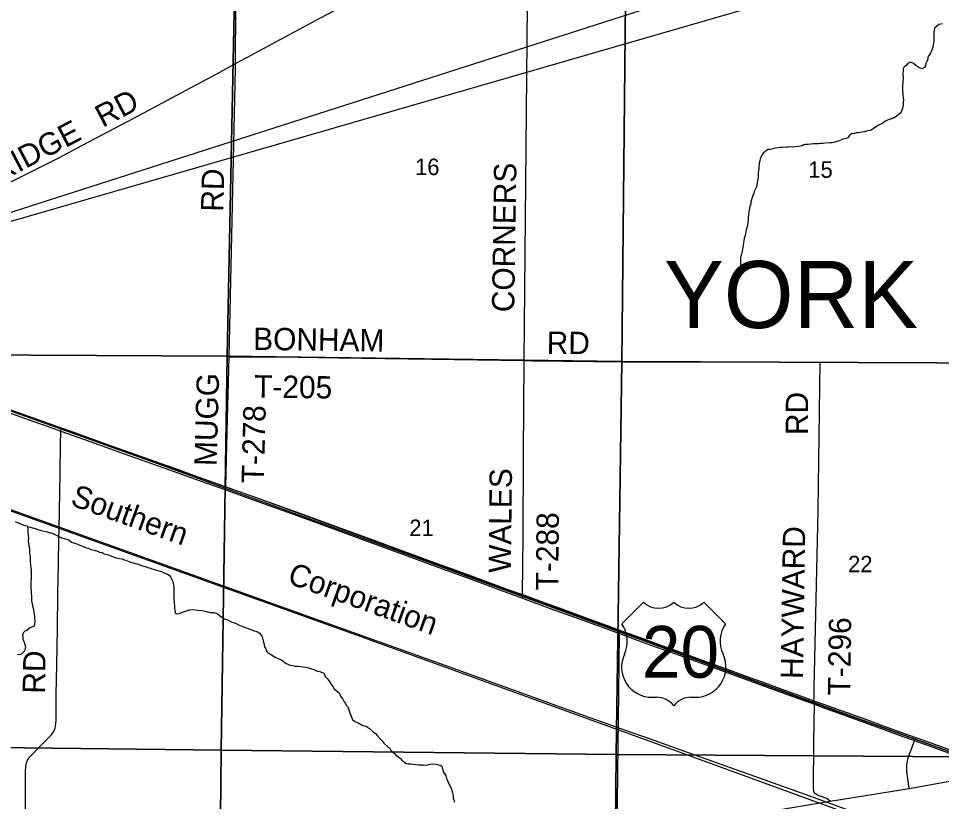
# Model space of a CAD drawing. Extents: x 0 to 34, y 0 to 22.
# Drawn here: x 4.651 to 6.998, y 16.061 to 18.051 of the extents above; entities that cross this region are included whole.
import ezdxf

# ---------------------------------------------------------------- set-up
doc = ezdxf.new("R2010")
doc.units = 0
for name, color, linetype in [('Default', 7, 'Continuous'), ('GM_X_County_Road', 7, 'Continuous'), ('GM_X_County_Road_Text', 7, 'Continuous'), ('GM_X_Minor_River', 7, 'Continuous'), ('GM_X_Rail_Line', 7, 'Continuous'), ('GM_X_Rail_Line_Text', 7, 'Continuous'), ('GM_X_Section', 7, 'Continuous'), ('GM_X_Section_Text', 7, 'Continuous'), ('GM_X_Township_Road', 7, 'Continuous'), ('GM_X_Township_Road_Text', 7, 'Continuous'), ('GM_X_Township_Text', 7, 'Continuous'), ('GM_X_US_Location', 7, 'Continuous'), ('GM_X_US_Route', 7, 'Continuous'), ('GM_X_US_Shield', 7, 'Continuous'), ('SH_Text', 7, 'Continuous')]:
    doc.layers.add(name, color=color, linetype=linetype)

msp = doc.modelspace()

# ---------------------------------------------------------------- linework, layer by layer
at = {"layer": 'Default'}
msp.add_lwpolyline([(3.8857, 17.3198), (5.25, 16.8357), (6.6044, 16.3383), (8.5432, 15.6366)], dxfattribs=at)
at = {"layer": 'GM_X_County_Road'}
for points in [[(4.5879, 17.6151), (4.6791, 17.6602), (4.7547, 17.6984), (4.8116, 17.7285), (4.9444, 17.7981), (5.0773, 17.8691), (5.1548, 17.9107), (5.2026, 17.9368), (5.2298, 17.9517), (5.3067, 17.9926), (5.3765, 18.0305), (5.4168, 18.0526), (5.4594, 18.0741), (5.5554, 18.1209), (5.7021, 18.1923), (5.7858, 18.2331), (5.8346, 18.2596), (5.9044, 18.2995), (5.9372, 18.3188), (5.9416, 18.3214)], [(6.7149, 16.0617), (6.9162, 16.094), (6.91, 16.1373), (6.9103, 16.1561), (6.9143, 16.1752), (6.9228, 16.1968), (6.9296, 16.2157), (6.9325, 16.2234)], [(4.6673, 15.5158), (4.8067, 15.5856), (4.9325, 15.6484), (4.9491, 15.6559), (4.9713, 15.6652), (5.0005, 15.6759), (5.0239, 15.6838), (5.165, 15.7242), (5.3194, 15.7665), (5.4913, 15.8144), (5.6607, 15.8606), (5.7319, 15.8819), (5.8085, 15.906), (5.8772, 15.9212), (5.9478, 15.9336), (6.1734, 15.9709), (6.2896, 15.9914), (6.4702, 16.0208), (6.7149, 16.0617)]]:
    msp.add_lwpolyline(points, dxfattribs=at)
at = {"layer": 'GM_X_Minor_River'}
for points in [[(7.0002, 18.0376), (6.996, 18.0368), (6.9915, 18.036), (6.9843, 18.0303), (6.9802, 18.0265), (6.9787, 18.0158), (6.9783, 18.0101), (6.9784, 17.9961), (6.9777, 17.9889), (6.9769, 17.9832), (6.9758, 17.9786), (6.9743, 17.9733), (6.9725, 17.9691), (6.9691, 17.9619), (6.9653, 17.9562), (6.9634, 17.952), (6.9631, 17.9478), (6.9608, 17.9417), (6.9586, 17.9367), (6.9571, 17.9314), (6.9548, 17.9269), (6.9484, 17.9234), (6.9408, 17.9272), (6.9328, 17.9321), (6.9267, 17.9374), (6.921, 17.9396), (6.9168, 17.9396), (6.9119, 17.9365), (6.9085, 17.932), (6.9032, 17.9285), (6.9009, 17.9232), (6.9002, 17.9171), (6.8999, 17.9129), (6.8999, 17.908), (6.9003, 17.9038), (6.9003, 17.8996), (6.9, 17.8932), (6.8996, 17.8871), (6.8992, 17.8825), (6.8989, 17.8768), (6.8989, 17.867), (6.8997, 17.8609), (6.8998, 17.8563), (6.9006, 17.8495), (6.901, 17.8446), (6.9006, 17.8385), (6.9003, 17.8332)], [(6.9003, 17.8332), (6.8995, 17.826), (6.898, 17.821), (6.8962, 17.8168), (6.8947, 17.8115), (6.8826, 17.8027), (6.8784, 17.8), (6.8739, 17.797), (6.8651, 17.795), (6.861, 17.7931), (6.8557, 17.7904), (6.8492, 17.7855), (6.8439, 17.7831), (6.8379, 17.7805), (6.8326, 17.777), (6.8265, 17.7724), (6.822, 17.7694), (6.8171, 17.7671), (6.8106, 17.7659), (6.8015, 17.7632), (6.7958, 17.7624), (6.7913, 17.762), (6.7863, 17.7608), (6.7822, 17.7604), (6.7772, 17.7593), (6.7693, 17.7581), (6.7632, 17.7535), (6.7598, 17.7482), (6.7545, 17.7466), (6.75, 17.7451), (6.7451, 17.7436), (6.7375, 17.7405), (6.7318, 17.7386), (6.7242, 17.7362), (6.7197, 17.7355), (6.7144, 17.7354), (6.7022, 17.7346), (6.6969, 17.7338), (6.6912, 17.7334), (6.6851, 17.733), (6.6779, 17.733), (6.6719, 17.7326), (6.6654, 17.7322), (6.6586, 17.7314), (6.6525, 17.731), (6.6476, 17.7306), (6.6434, 17.7279), (6.6335, 17.7256), (6.626, 17.7248), (6.6184, 17.7247), (6.6131, 17.7251), (6.6085, 17.7247), (6.6036, 17.7243), (6.5926, 17.7238), (6.5876, 17.7234), (6.5831, 17.723), (6.5755, 17.7219), (6.5706, 17.7207), (6.5664, 17.7195), (6.5615, 17.7188), (6.5573, 17.718), (6.5527, 17.7161), (6.5448, 17.7088), (6.5407, 17.702), (6.5373, 17.6943), (6.5362, 17.6898), (6.5347, 17.6833), (6.5336, 17.6734), (6.5336, 17.6693), (6.5318, 17.6601), (6.5314, 17.656), (6.5315, 17.6468), (6.5304, 17.6385), (6.5292, 17.6339), (6.5285, 17.6297), (6.5274, 17.6236), (6.5218, 17.6118), (6.521, 17.6077), (6.5173, 17.5993), (6.5135, 17.5852), (6.5128, 17.5803), (6.5106, 17.5731), (6.5091, 17.5651), (6.5072, 17.5521), (6.5065, 17.5468), (6.5065, 17.5396), (6.5054, 17.5328), (6.5047, 17.5248), (6.5017, 17.5141), (6.5006, 17.51), (6.4995, 17.505), (6.4984, 17.5004), (6.4965, 17.4921), (6.4954, 17.4864), (6.494, 17.4757), (6.4932, 17.47), (6.4921, 17.4647), (6.491, 17.459), (6.4891, 17.4522), (6.488, 17.4476), (6.4873, 17.4423)], [(6.4873, 17.4423), (6.4866, 17.4366), (6.4867, 17.4108)], [(4.642, 16.7729), (4.6519, 16.7684), (4.6671, 16.7628), (4.6732, 16.7613), (4.6744, 16.7537), (4.6748, 16.7492), (4.6748, 16.7439), (4.6752, 16.7397), (4.6756, 16.7359), (4.676, 16.7317), (4.6753, 16.723), (4.6761, 16.7169), (4.6773, 16.7108), (4.6784, 16.7051), (4.6785, 16.6983), (4.6792, 16.693), (4.6797, 16.688), (4.6801, 16.6808), (4.6805, 16.6732), (4.6809, 16.6694), (4.6813, 16.6645), (4.6817, 16.6607), (4.6821, 16.6558), (4.6829, 16.6497), (4.6833, 16.6451), (4.6833, 16.6315), (4.683, 16.6258)], [(4.6734, 16.7603), (4.6934, 16.755), (4.6998, 16.752), (4.7063, 16.7508), (4.712, 16.749), (4.7215, 16.7471), (4.731, 16.7441), (4.7367, 16.7426), (4.7451, 16.7385), (4.7508, 16.7359), (4.755, 16.734), (4.761, 16.7313), (4.7664, 16.7291), (4.7789, 16.7257), (4.7858, 16.7201), (4.7941, 16.7178), (4.8135, 16.7099), (4.8238, 16.7058), (4.8291, 16.7047), (4.8345, 16.7017), (4.8432, 16.6998), (4.8516, 16.6972), (4.8569, 16.695), (4.8633, 16.6939), (4.8691, 16.6908), (4.877, 16.6886), (4.8873, 16.6848), (4.8945, 16.6818), (4.8991, 16.6807), (4.9078, 16.6785), (4.9143, 16.6774), (4.9196, 16.6755), (4.9242, 16.674), (4.9318, 16.6706), (4.9386, 16.6688), (4.9428, 16.6676), (4.9478, 16.6661), (4.9535, 16.6647), (4.9614, 16.6613), (4.9671, 16.6602), (4.9755, 16.6572), (4.982, 16.6553), (4.9861, 16.6542), (4.9903, 16.6527), (4.9945, 16.6516), (5.0021, 16.6493), (5.0074, 16.6471), (5.0143, 16.6456), (5.0227, 16.6414), (5.0295, 16.6384), (5.0341, 16.6365), (5.0371, 16.6324), (5.0406, 16.6252), (5.0433, 16.6203), (5.044, 16.6157), (5.0448, 16.6104), (5.046, 16.6055), (5.046, 16.6013), (5.046, 16.5963), (5.0461, 16.5743), (5.0466, 16.5679), (5.0474, 16.5557), (5.0478, 16.5508), (5.049, 16.5443), (5.0494, 16.5394), (5.0539, 16.5379), (5.0592, 16.5387), (5.0729, 16.5437), (5.0861, 16.5483), (5.0945, 16.5487), (5.1066, 16.5476), (5.1176, 16.5462), (5.1287, 16.5439), (5.1385, 16.5417), (5.1431, 16.5417), (5.1477, 16.5414), (5.1526, 16.5399), (5.1568, 16.5376), (5.1617, 16.5338), (5.1678, 16.5297), (5.1747, 16.5252), (5.1827, 16.5229), (5.1933, 16.5165), (5.2032, 16.5139), (5.2082, 16.5109), (5.2135, 16.5083), (5.2196, 16.5068), (5.2264, 16.503), (5.2336, 16.5011), (5.2382, 16.4993), (5.2443, 16.4974), (5.2492, 16.4947), (5.2546, 16.4936), (5.2599, 16.4914), (5.2641, 16.4884), (5.2683, 16.4834), (5.2706, 16.4793), (5.2729, 16.469), (5.2748, 16.4637), (5.2764, 16.4542), (5.2795, 16.4489)], [(4.683, 16.6258), (4.6823, 16.6193), (4.6819, 16.6155), (4.682, 16.6064), (4.6824, 16.6011), (4.6828, 16.5973), (4.6832, 16.5897), (4.6836, 16.5844), (4.6836, 16.5756), (4.684, 16.5711), (4.686, 16.5631), (4.6875, 16.5547), (4.6887, 16.5491), (4.6895, 16.5422), (4.6903, 16.5369), (4.6911, 16.5312), (4.6918, 16.5263), (4.6923, 16.5213), (4.6923, 16.5172), (4.6915, 16.5107), (4.6904, 16.5069), (4.6791, 16.5011), (4.6723, 16.4958), (4.6673, 16.4935), (4.6636, 16.4901), (4.6613, 16.484), (4.6617, 16.4775), (4.6621, 16.4737), (4.6652, 16.4661), (4.6667, 16.4597), (4.6683, 16.454), (4.6679, 16.4498), (4.6657, 16.4433), (4.6597, 16.4365), (4.6559, 16.4346), (4.6479, 16.4338)], [(5.2795, 16.4489), (5.2825, 16.4425), (5.2863, 16.4379), (5.2943, 16.4338), (5.3035, 16.4274), (5.3088, 16.4255), (5.3179, 16.4218), (5.3229, 16.4184), (5.3297, 16.4127), (5.3355, 16.4097), (5.3412, 16.4074), (5.3484, 16.4063), (5.3541, 16.4052), (5.3632, 16.4045), (5.3742, 16.403), (5.3814, 16.4027), (5.3883, 16.4004), (5.3936, 16.3993), (5.4016, 16.3963), (5.4103, 16.3926), (5.4168, 16.3911), (5.4225, 16.3888), (5.427, 16.3877), (5.4305, 16.379), (5.4355, 16.3733), (5.4389, 16.3692), (5.4435, 16.3635), (5.4469, 16.3574), (5.4511, 16.3525), (5.4531, 16.3483), (5.4626, 16.3396), (5.4668, 16.3362), (5.4683, 16.3321), (5.4714, 16.326), (5.4752, 16.3207), (5.479, 16.3146), (5.4825, 16.3101), (5.4844, 16.3056), (5.4882, 16.3014), (5.4905, 16.2938), (5.4936, 16.2866), (5.4948, 16.282), (5.4967, 16.2779), (5.5001, 16.2695), (5.5062, 16.2643), (5.5142, 16.2609), (5.5245, 16.2548), (5.5355, 16.2515), (5.5435, 16.2466), (5.5527, 16.2379), (5.5588, 16.2341), (5.5634, 16.2277), (5.5718, 16.2194), (5.5756, 16.2148), (5.5798, 16.2088), (5.5897, 16.2001), (5.5939, 16.1971), (5.5969, 16.1925), (5.6008, 16.1876), (5.6053, 16.185), (5.6107, 16.1789), (5.6149, 16.1763), (5.6221, 16.1706), (5.6267, 16.1649), (5.6316, 16.1619), (5.6366, 16.1577), (5.6415, 16.1563), (5.6476, 16.1563), (5.6552, 16.1556), (5.6601, 16.1552), (5.6677, 16.1541), (5.6799, 16.1538), (5.686, 16.1534), (5.692, 16.1542), (5.6973, 16.1554), (5.7046, 16.1562), (5.7114, 16.1554), (5.7194, 16.1543), (5.7235, 16.1532), (5.7277, 16.151), (5.7281, 16.1468), (5.7297, 16.1415), (5.732, 16.1354), (5.735, 16.1305), (5.7373, 16.1263), (5.7389, 16.1191), (5.7416, 16.1142), (5.7446, 16.1077), (5.7481, 16.1013), (5.7523, 16.0922), (5.7535, 16.0865), (5.7554, 16.0789), (5.7558, 16.0736), (5.7566, 16.069), (5.7585, 16.063), (5.7589, 16.0588)]]:
    msp.add_lwpolyline(points, dxfattribs=at)
at = {"layer": 'GM_X_Rail_Line'}
for points in [[(2.3438, 17.8832), (3.2394, 17.556), (3.7037, 17.3885), (4.1527, 17.2251), (5.0251, 16.9129), (5.72, 16.6602), (6.7111, 16.2981), (7.2308, 16.1113), (7.9999, 15.8344), (8.5456, 15.6361), (8.9, 15.5035)], [(2.1205, 17.682), (2.6475, 17.5103), (3.1194, 17.3438), (3.8981, 17.0634), (4.4129, 16.8774), (5.5123, 16.484), (6.2938, 16.2008), (7.1773, 15.8785), (7.9469, 15.6046), (8.6994, 15.3378), (8.9, 15.264)], [(4.3626, 16.8993), (4.9898, 16.6747), (5.3844, 16.533), (5.7561, 16.3995), (6.08, 16.2832), (6.1965, 16.2416), (6.2568, 16.2199), (6.33, 16.1936), (6.5817, 16.1037), (6.6739, 16.0713), (6.9385, 15.9745), (7.0187, 15.9431)]]:
    msp.add_lwpolyline(points, dxfattribs=at)
at = {"layer": 'GM_X_Section'}
for points in [[(4.1997, 18.1993), (5.2018, 18.1949), (5.1818, 17.1932), (4.1831, 17.1984)], [(5.2018, 18.1949), (6.1951, 18.1802), (6.185, 17.1797), (5.1818, 17.1932)], [(7.2022, 18.181), (7.1859, 17.1752), (6.185, 17.1797), (6.1951, 18.1802)], [(4.1831, 17.1984), (5.1818, 17.1932), (5.166, 16.1912), (4.1651, 16.2036)], [(5.1818, 17.1932), (6.185, 17.1797), (6.1703, 16.1807), (5.166, 16.1912)], [(6.185, 17.1797), (7.1859, 17.1752), (7.1762, 16.1739), (6.1703, 16.1807)], [(4.1651, 16.2036), (5.166, 16.1912), (5.1562, 15.1911), (4.1541, 15.2001)], [(5.166, 16.1912), (6.1703, 16.1807), (6.1617, 15.1831), (5.1562, 15.1911)], [(7.1762, 16.1739), (7.1686, 15.1654), (6.1617, 15.1831), (6.1703, 16.1807)]]:
    msp.add_lwpolyline(points, close=True, dxfattribs=at)
at = {"layer": 'GM_X_Township_Road'}
msp.add_line((6.9162, 16.094), (7.0561, 16.1195), dxfattribs=at)
for points in [[(5.2027, 17.9498), (5.2148, 19.617), (5.2148, 19.7745), (5.2168, 19.9602), (5.2193, 20.1515), (5.2185, 20.2104), (5.2187, 20.22), (5.2204, 20.2273), (5.2209, 20.2283), (5.2253, 20.2361), (5.2264, 20.238)], [(5.9368, 17.1818), (5.9465, 18.1768), (5.9503, 18.3268)], [(5.1865, 17.1917), (5.2025, 17.924), (5.2026, 17.9368), (5.2027, 17.9498)], [(5.1784, 16.8529), (5.1785, 16.8612), (5.1827, 17.0344), (5.1854, 17.1595), (5.1865, 17.1917)], [(5.1865, 17.1917), (5.3114, 17.1916), (5.4642, 17.1891), (5.9368, 17.1818), (5.9591, 17.1811), (6.1898, 17.1786), (6.6892, 17.1776), (7.1906, 17.1758)], [(5.9322, 16.578), (5.9323, 16.5867), (5.9339, 16.7333), (5.935, 16.9442), (5.9368, 17.1818)], [(6.6824, 16.7244), (6.684, 16.8014), (6.6892, 17.1776)], [(4.7539, 16.7519), (4.7547, 16.7997), (4.7566, 16.8939), (4.7576, 16.9678), (4.7587, 17.0023), (4.7591, 17.0108)], [(4.6683, 16.0047), (4.6686, 16.0899), (4.6689, 16.1374), (4.6695, 16.1492), (4.6711, 16.1594), (4.6735, 16.1661), (4.6794, 16.1748), (4.7075, 16.2029), (4.7338, 16.2297), (4.7409, 16.239), (4.7442, 16.2481), (4.7456, 16.2583), (4.7463, 16.2684), (4.7469, 16.333), (4.7484, 16.4091), (4.7501, 16.4993), (4.751, 16.5903), (4.7522, 16.6632), (4.7536, 16.732), (4.7539, 16.7519)], [(6.6738, 16.3172), (6.6739, 16.3274), (6.6746, 16.3501), (6.6824, 16.7244)], [(6.1734, 15.9709), (6.1751, 16.1354), (6.1772, 16.3363), (6.1789, 16.4878), (6.1793, 16.4965)], [(6.6738, 16.2113), (6.675, 16.308), (6.6738, 16.3172)], [(6.7149, 16.0617), (6.7063, 16.0686), (6.6845, 16.0759), (6.6776, 16.08), (6.6738, 16.0856), (6.6724, 16.0952), (6.6738, 16.2113)]]:
    msp.add_lwpolyline(points, dxfattribs=at)
at = {"layer": 'GM_X_US_Route'}
for p, q in [((6.6738, 16.3172), (6.7029, 16.3067)), ((6.675, 16.308), (6.7032, 16.2977))]:
    msp.add_line(p, q, dxfattribs=at)
for points in [[(4.597, 17.0599), (4.6755, 17.032), (4.726, 17.0139), (4.7587, 17.0023), (4.8333, 16.9758), (4.9336, 16.9398), (5.02, 16.9091), (5.1128, 16.8759), (5.1784, 16.8529), (5.2499, 16.827), (5.3571, 16.7884), (5.452, 16.7538), (5.5447, 16.7199), (5.6302, 16.6886), (5.7102, 16.6592), (5.8019, 16.6258), (5.8953, 16.5914), (5.9322, 16.578), (6.0032, 16.5518), (6.0819, 16.5234), (6.1789, 16.4878), (6.2468, 16.4628), (6.3338, 16.4318), (6.4265, 16.3982), (6.5107, 16.3677), (6.5986, 16.3358), (6.6487, 16.3175), (6.675, 16.308)], [(4.619, 17.0609), (4.676, 17.0405), (4.7264, 17.0225), (4.7591, 17.0108), (4.7841, 17.002), (4.8276, 16.9862), (4.877, 16.9688), (4.9352, 16.948), (5.0059, 16.9228), (5.0502, 16.907), (5.1046, 16.8874), (5.1403, 16.8747), (5.1785, 16.8612), (5.25, 16.8357), (5.3572, 16.7971), (5.4521, 16.7625), (5.5448, 16.7286), (5.6303, 16.6974), (5.7103, 16.6679), (5.7536, 16.6522), (5.802, 16.6345), (5.8954, 16.6001), (5.9323, 16.5867), (5.9482, 16.5808), (5.9895, 16.566), (6.0256, 16.5528), (6.0822, 16.532), (6.1476, 16.508), (6.1793, 16.4965), (6.2407, 16.4742), (6.2839, 16.4586), (6.3326, 16.441), (6.4057, 16.4143), (6.449, 16.3986), (6.4989, 16.3807), (6.5422, 16.3648), (6.599, 16.3442), (6.6492, 16.3262), (6.6738, 16.3172)], [(6.7029, 16.3067), (6.7077, 16.305), (6.743, 16.2921), (6.8072, 16.2691), (6.8499, 16.2535), (6.9013, 16.235), (6.9325, 16.2234)], [(6.7032, 16.2977), (6.7277, 16.2888), (6.807, 16.2601), (6.9001, 16.2262), (6.9296, 16.2157), (6.9639, 16.2031), (6.9996, 16.1902), (7.0573, 16.1692), (7.0939, 16.1559), (7.1152, 16.1482), (7.1512, 16.1353), (7.1578, 16.133)], [(6.9325, 16.2234), (6.9655, 16.2117), (7.0012, 16.1987), (7.0586, 16.1778), (7.0943, 16.1649), (7.1174, 16.1564)]]:
    msp.add_lwpolyline(points, dxfattribs=at)
at = {"layer": 'GM_X_US_Shield'}
for p, q in [((6.2402, 16.5676), (6.1852, 16.5127)), ((6.4489, 16.5127), (6.394, 16.5676)), ((6.2621, 16.3259), (6.2731, 16.3259)), ((6.361, 16.3259), (6.372, 16.3259))]:
    msp.add_line(p, q, dxfattribs=at)
for centre, radius, start, end in [((6.2786, 16.6069), 0.0549, 225.573, 314.427), ((6.3555, 16.6069), 0.0549, 225.573, 314.427), ((6.1222, 16.4686), 0.0769, 334.5471, 35.0009), ((6.5119, 16.4686), 0.0769, 144.9991, 205.4529), ((6.2613, 16.4028), 0.0769, 154.8319, 270.6383), ((6.3729, 16.4028), 0.0769, 269.3617, 25.1681), ((6.2731, 16.271), 0.0549, 36.8699, 90), ((6.361, 16.271), 0.0549, 90, 143.1301)]:
    msp.add_arc(centre, radius, start, end, dxfattribs=at)
at = {"layer": 'SH_Text'}
msp.add_lwpolyline([(3.8857, 17.3198), (9.3048, 19.0572), (9.3048, 18.8857)], close=True, dxfattribs=at)

# ---------------------------------------------------------------- texts
at = {"layer": 'GM_X_County_Road_Text'}
for s, rotation, p in [('RD', 27.667, (4.865, 17.7731)), ('RIDGE', 27.6279, (4.6017, 17.6339))]:
    msp.add_text(s, height=0.05682, rotation=rotation, dxfattribs=at).set_placement(p)
at = {"layer": 'GM_X_Rail_Line_Text'}
for s, height, rotation, p in [('Southern', 0.05663, 340.212, (4.7803, 16.815)), ('Corporation', 0.056629, 340.2813, (5.3319, 16.6167))]:
    msp.add_text(s, height=height, rotation=rotation, dxfattribs=at).set_placement(p)
at = {"layer": 'GM_X_Section_Text'}
for s, p in [('16', (5.6592, 17.6533)), ('15', (6.6592, 17.6464)), ('21', (5.6446, 16.7357)), ('22', (6.7604, 16.6436))]:
    msp.add_text(s, height=0.04186, rotation=0, dxfattribs=at).set_placement(p)
at = {"layer": 'GM_X_Township_Road_Text'}
for s, rotation, p in [('CORNERS', 89.1275, (5.9114, 17.3044)), ('RD', 88.5175, (5.1714, 17.5597)), ('BONHAM', 359.2259, (5.2474, 17.209)), ('RD', 359.5063, (5.9939, 17.1989)), ('MUGG', 88.4276, (5.1547, 16.9131)), ('T-205', 359.1579, (5.2498, 17.088)), ('RD', 90, (6.6589, 16.9924)), ('T-278', 88.5957, (5.2748, 16.8692)), ('WALES', 89.4014, (5.9031, 16.6418)), ('T-288', 89.4386, (6.0232, 16.5973)), ('HAYWARD', 89.0781, (6.6456, 16.372)), ('T-296', 89.1579, (6.7657, 16.3302)), ('RD', 89.0128, (4.7181, 16.3345))]:
    msp.add_text(s, height=0.05682, rotation=rotation, dxfattribs=at).set_placement(p)
at = {"layer": 'GM_X_Township_Text'}
msp.add_text('YORK', height=0.17045, rotation=0, dxfattribs=at).set_placement((6.2925, 17.2645))
at = {"layer": 'GM_X_US_Location'}
for s in ['0', '/']:
    msp.add_text(s, height=0.000189, dxfattribs=at).set_placement((6.317, 16.4403))
msp.add_text('20', height=0.000189, rotation=0, dxfattribs=at).set_placement((6.2779, 16.4011))
at = {"layer": 'GM_X_US_Shield'}
msp.add_text('20', height=0.13184, dxfattribs=at).set_placement((6.2362, 16.3754))

doc.saveas('drawing.dxf')
